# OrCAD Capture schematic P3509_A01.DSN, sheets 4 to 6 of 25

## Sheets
4 0021_M.2 KEY-M (NVME): size Custom
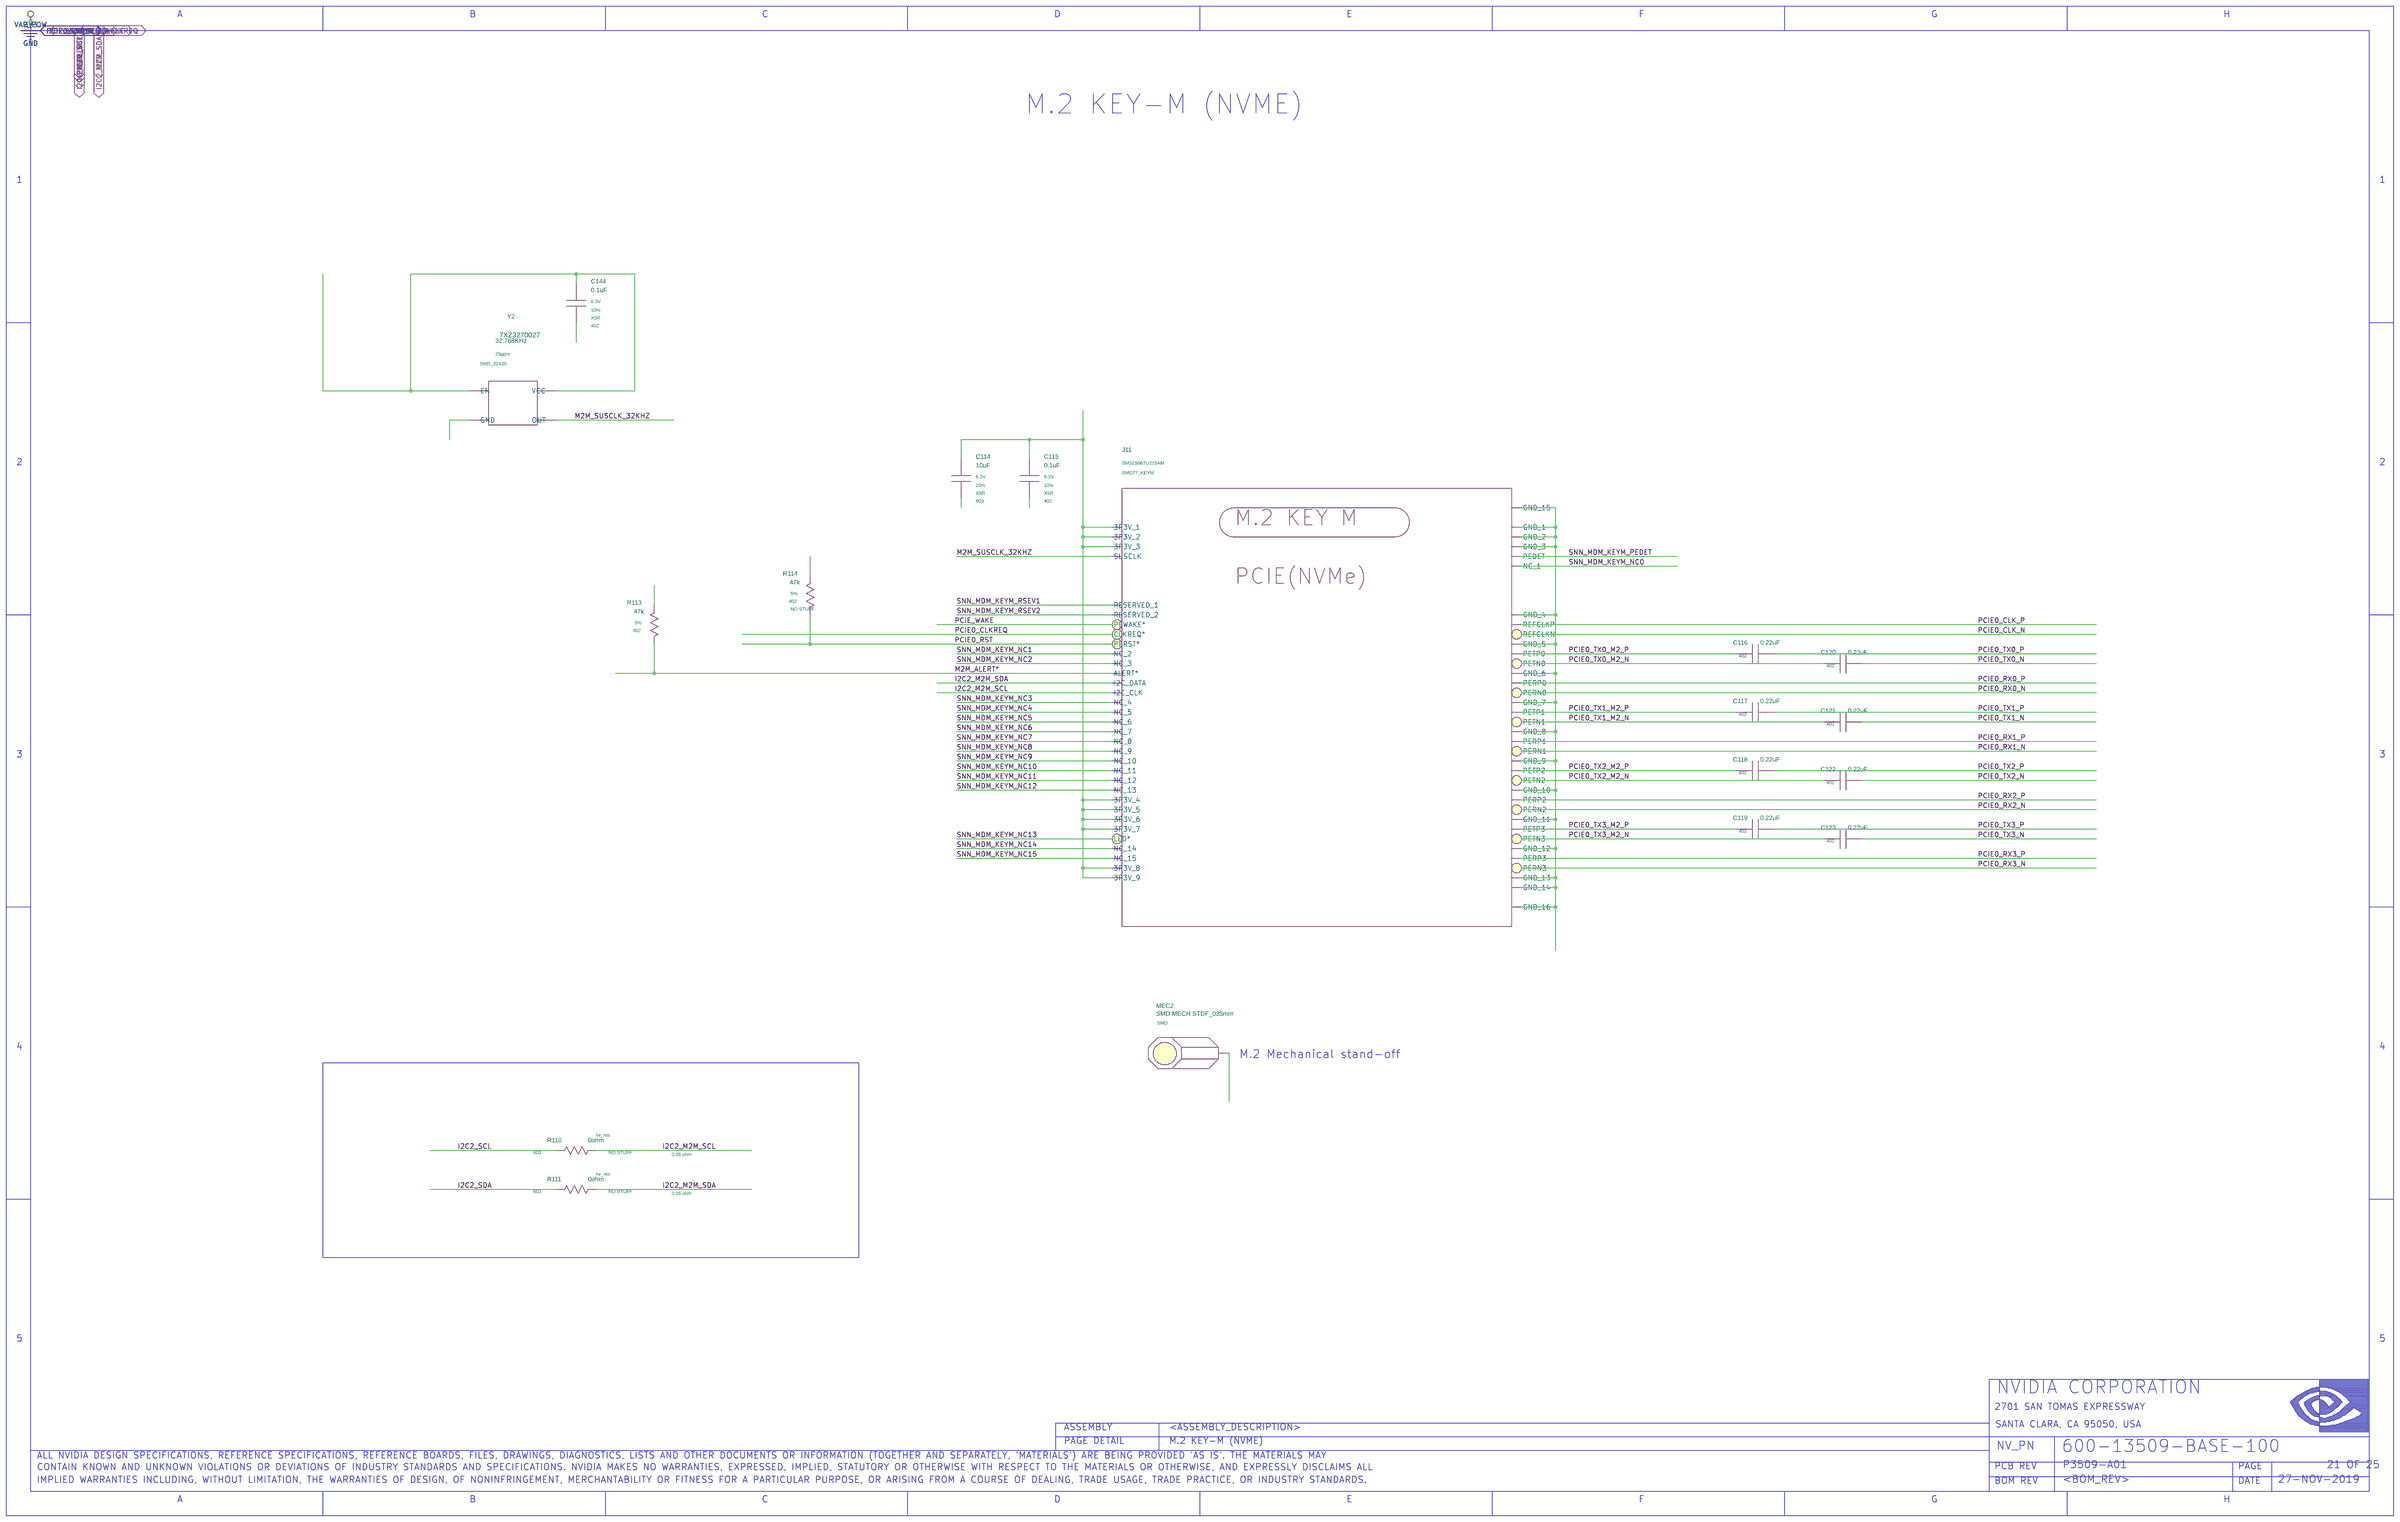
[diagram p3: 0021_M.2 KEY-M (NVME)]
5 0020_M.2 KEY-E (WIFI_BT): size Custom
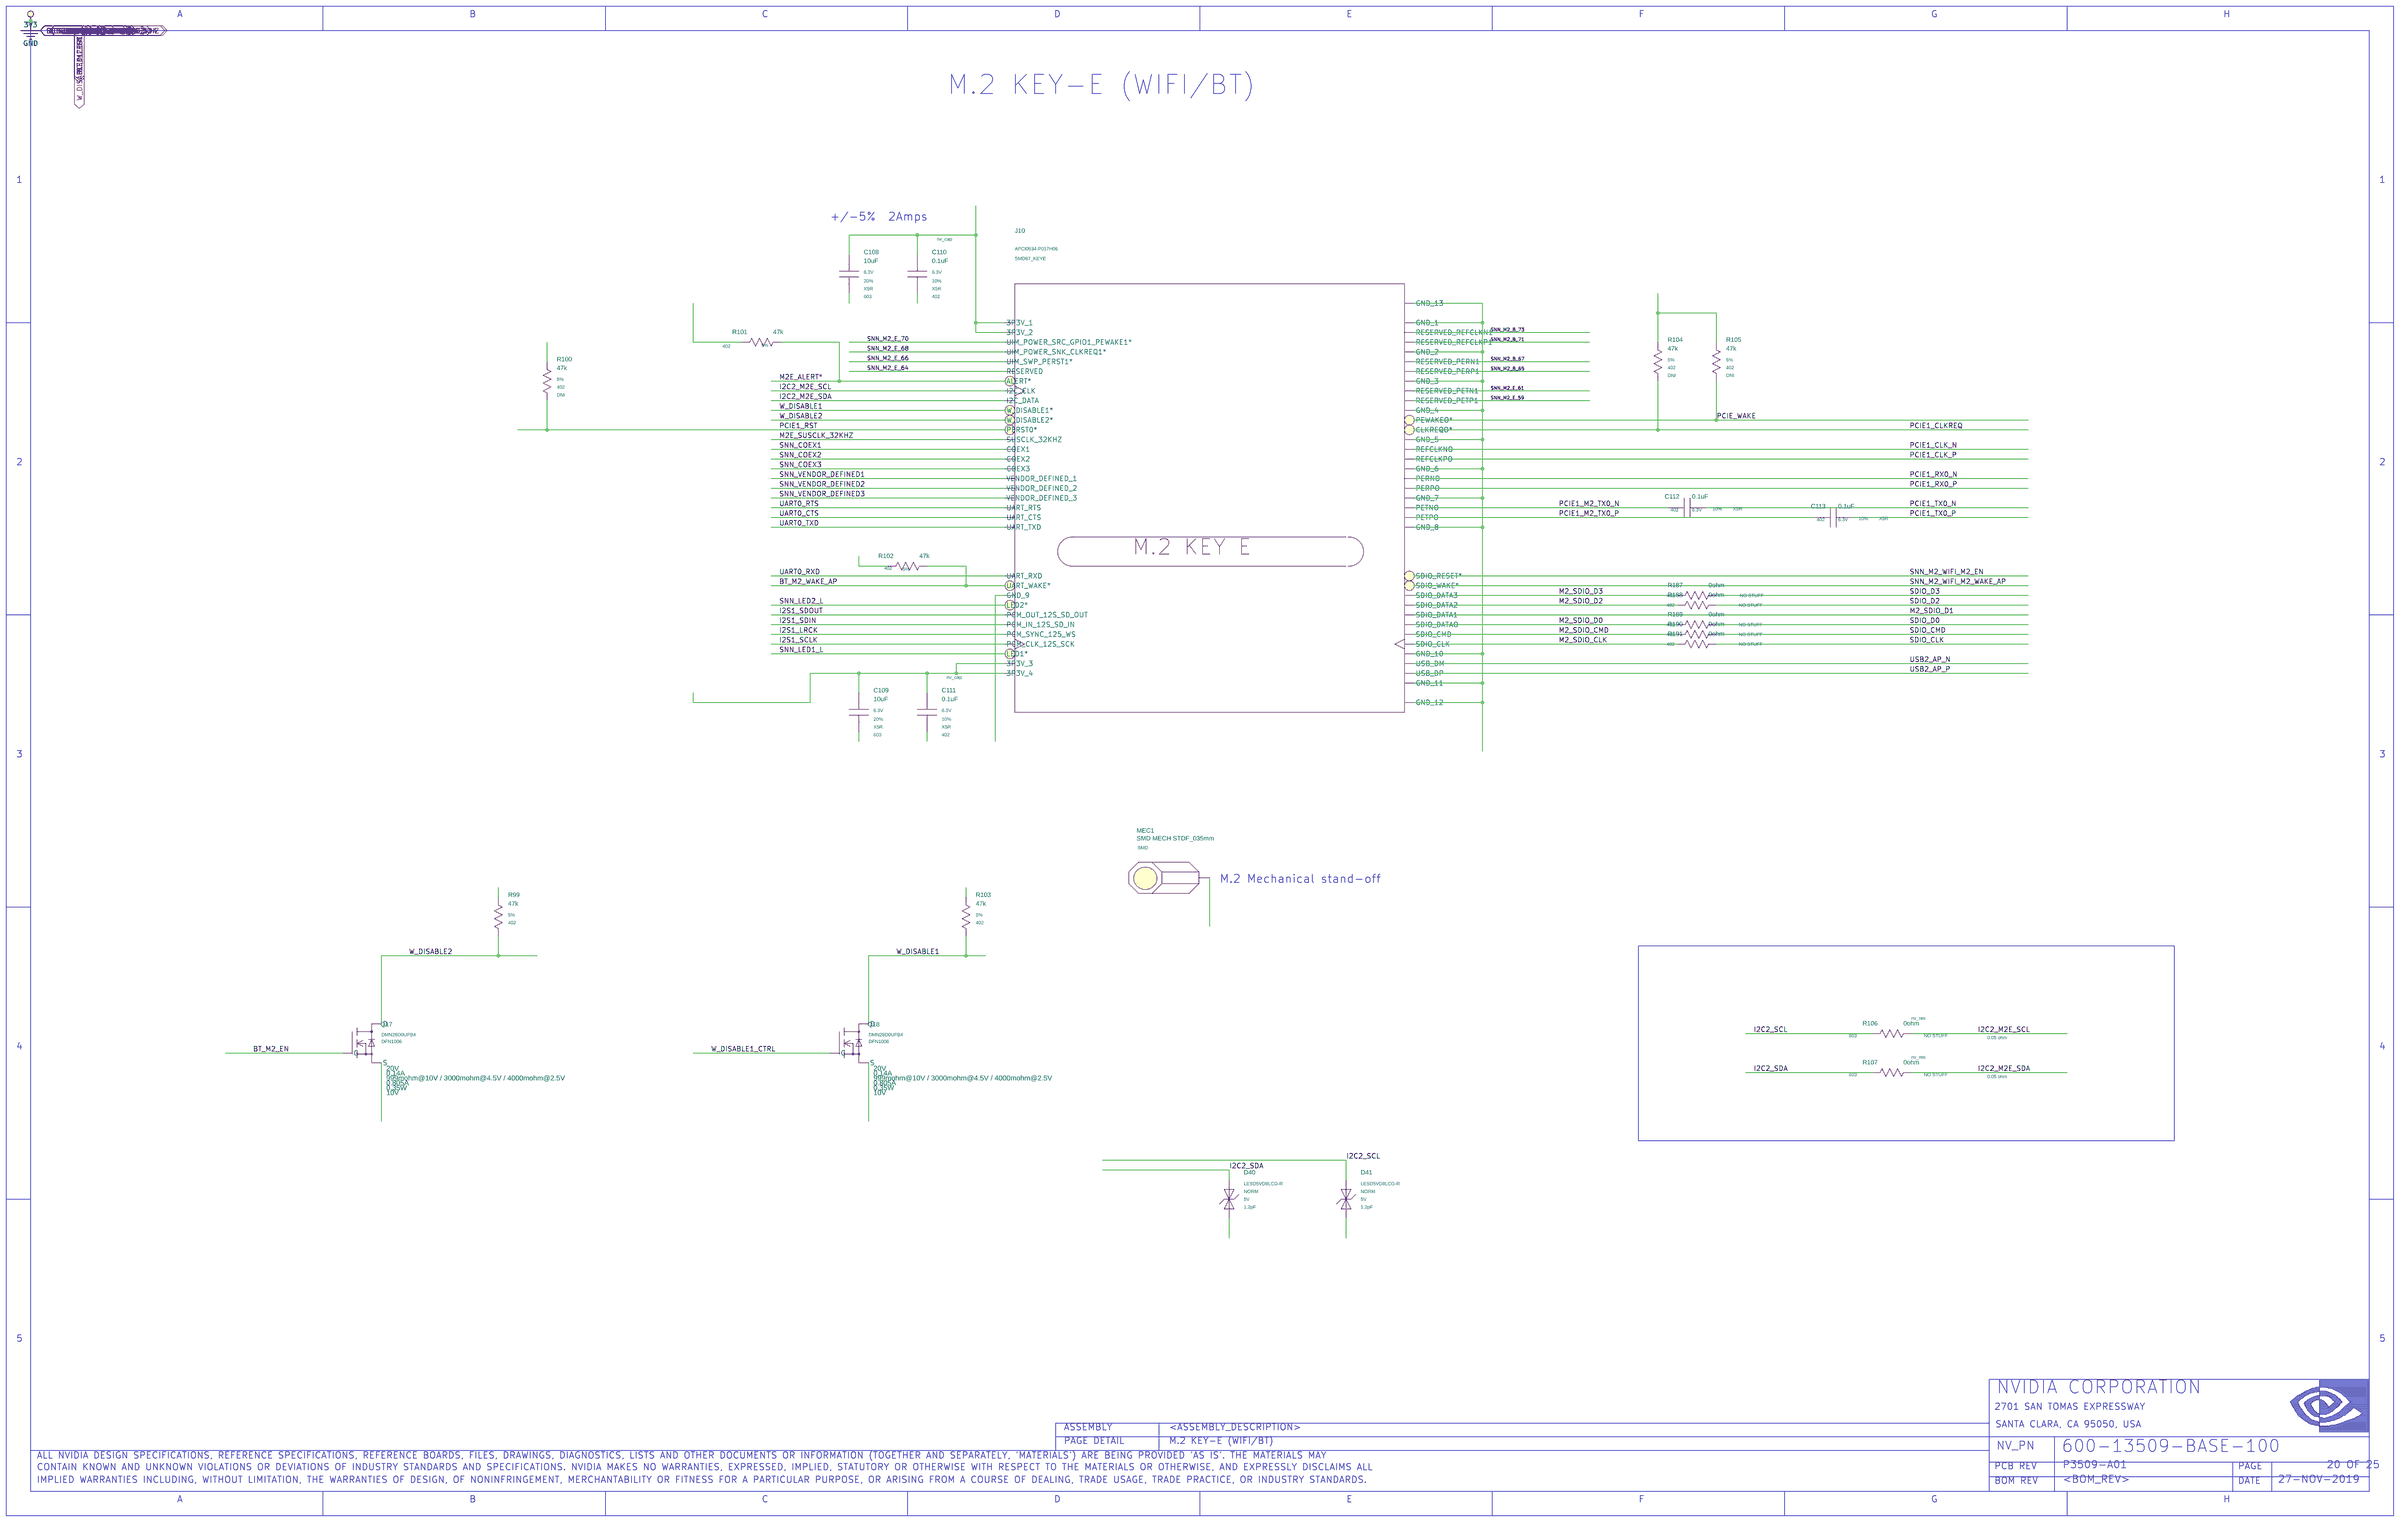
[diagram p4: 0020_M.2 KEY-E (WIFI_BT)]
6 0019_ETHERNET: size Custom
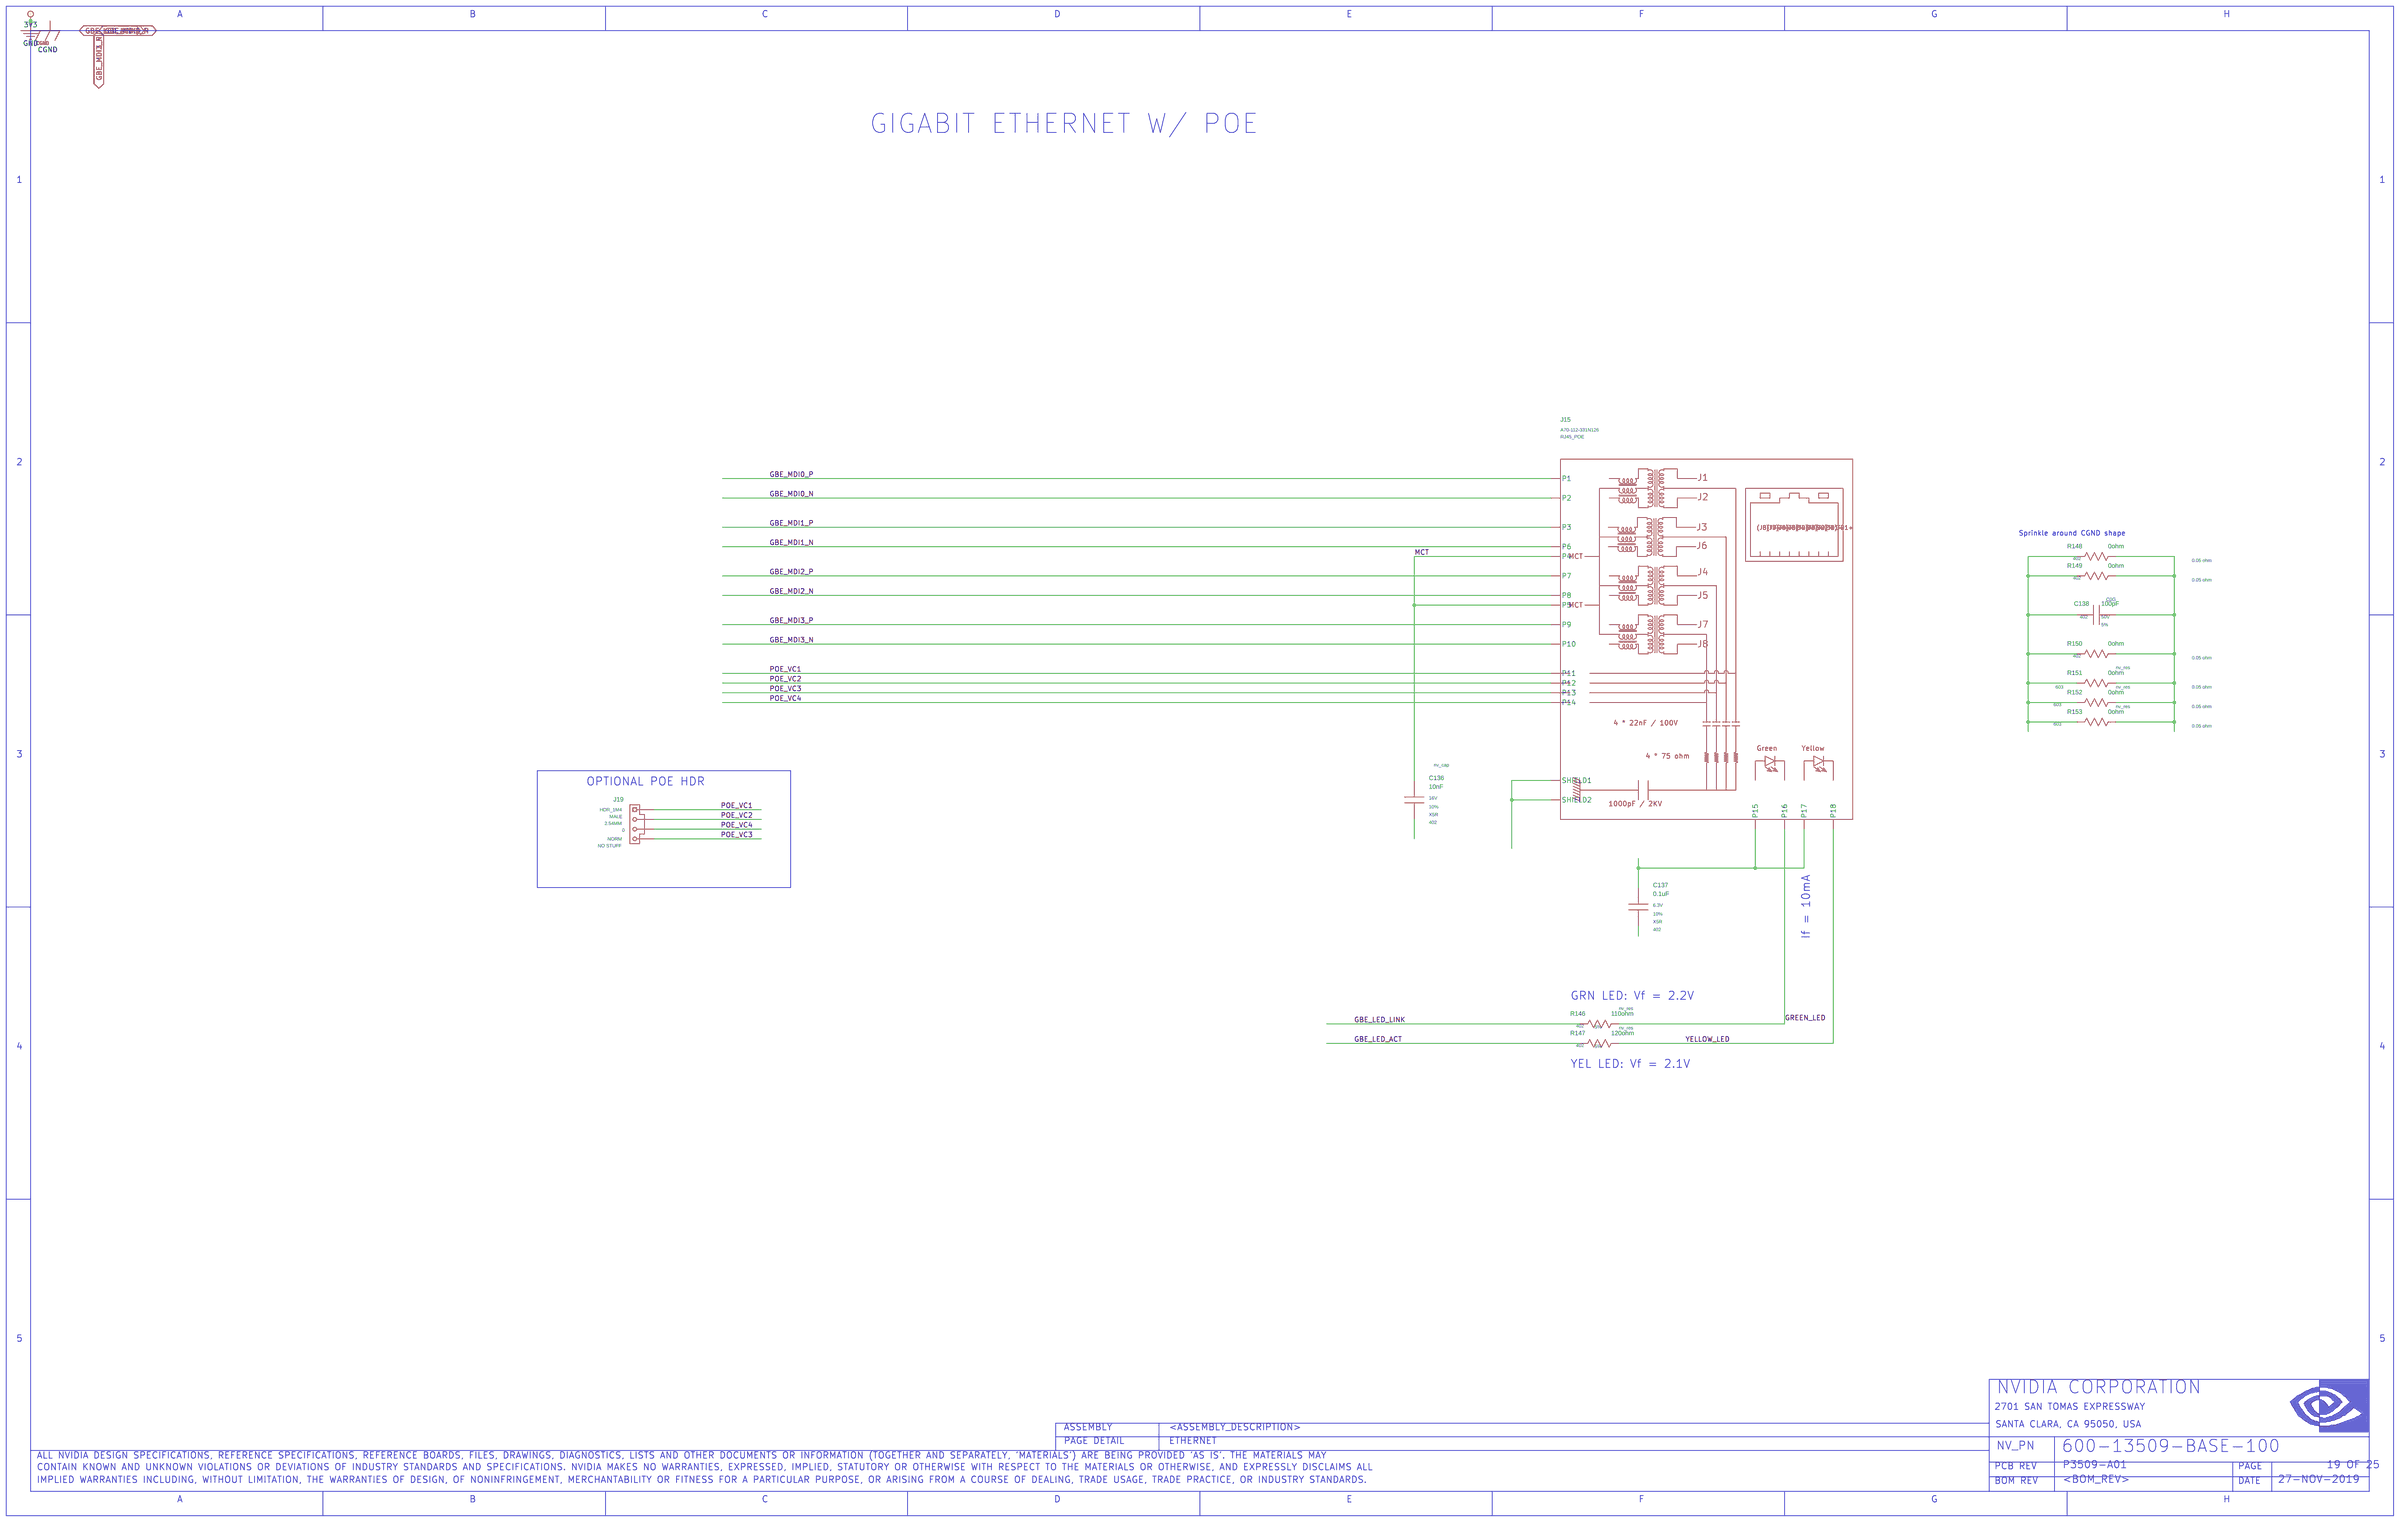
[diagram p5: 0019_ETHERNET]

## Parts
sheet 0019_ETHERNET
C136  10nF  [402]
C137  0.1uF  [402]
C138  100pF  [402]
J15  CON_RJ45  [CON_RJ45_018_TH_RA_F_2LED]
J19  HDR_1X4  [CON_HDR_001X004_TH_ST_M_P025]
R146  110ohm  [402]
R147  120ohm  [402]
R148  0ohm  [402]
R149  0ohm  [402]
R150  0ohm  [402]
R151  0ohm  [603]
R152  0ohm  [603]
R153  0ohm  [603]
sheet 0020_M.2 KEY-E (WIFI_BT)
C108  10uF  [603]
C109  10uF  [603]
C110  0.1uF  [402]
C111  0.1uF  [402]
C112  0.1uF  [402]
C113  0.1uF  [402]
D40  D_ESD  [DIODE_SMD_010X060]
D41  D_ESD  [DIODE_SMD_010X060]
J10  CON_M2_PCI_EXP  [CON_MINIPEX_067_SMT_RA_M2_KEYE_C]
MEC1  MEC_STANDOFF  [MEC_STANDOFF_PTH_620C380P]
Q17  Q_FET_N_ENH  [DFET_003_SMD_010X006_B]
Q18  Q_FET_N_ENH  [DFET_003_SMD_010X006_B]
R99  47k  [402]
R100  47k  [402]
R101  47k  [402]
R102  47k  [402]
R103  47k  [402]
R104  47k  [402]
R105  47k  [402]
R106  0ohm  [603]
R107  0ohm  [603]
R187  0ohm  [402]
R188  0ohm  [402]
R189  0ohm  [402]
R190  0ohm  [402]
R191  0ohm  [402]
sheet 0021_M.2 KEY-M (NVME)
C114  10uF  [603]
C115  0.1uF  [402]
C116  0.22uF  [402]
C117  0.22uF  [402]
C118  0.22uF  [402]
C119  0.22uF  [402]
C120  0.22uF  [402]
C121  0.22uF  [402]
C122  0.22uF  [402]
C123  0.22uF  [402]
C144  0.1uF  [402]
J11  CON_M2_PCI_EXP  [CON_MINIPEX_075_SMT_RA_M2_KEYM]
MEC2  MEC_STANDOFF  [MEC_STANDOFF_PTH_620C380P]
R110  0ohm  [603]
R111  0ohm  [603]
R113  47k  [402]
R114  47k  [402]
Y2  32.768KHz  [XTAL_SMD_4_032X025_D]

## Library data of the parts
C136 = C#1_v2: ASSEMBLY: ETHERNET; CDS_LIB: discrete; CDS_PART_NAME: C_0402-10NF,X5R,10%,16V,039-0024-000; CDS_PHYS_PART_NAME: C_0402-10NF,X5R,10%,16V,039-0024-000-039-0024-000,10NF; CDS_SEC: 1; CHIPS_PART_NAME: C; DEVICE_TYPENAME: C_0402-10NFX5R1016V039-0024-000-039-0024-00010NF; DRAWING: #NAME?; MAT: X5R; MAX_VOLTAGE: 16V; NV_PN: 039-0024-000; PATH: I15; PHYS_PAGE: 19; ROT: 0; SEC: 1; SIGNAL_MODEL: nv_cap; TOL: 10%; VER: 1; XY: (-4900,3550)
C137 = C#1_v2: ASSEMBLY: ETHERNET; CDS_LIB: discrete; CDS_PART_NAME: C_0402-0.1UF,X5R,10%,6.3V,039-0007-000; CDS_PHYS_PART_NAME: C_0402-0.1UF,X5R,10%,6.3V,039-0007-000-0.1UF,039-0007-000; CDS_SEC: 1; CHIPS_PART_NAME: C; DEVICE_TYPENAME: C_0402-01UFX5R1063V039-0007-000-01UF039-0007-000; DRAWING: #NAME?; ESL: N/A; ESR: N/A; MAT: X5R; MAX_VOLTAGE: 6.3V; NV_PN: 039-0007-000; PATH: I13; PHYS_PAGE: 19; ROT: 0; SEC: 1; SIGNAL_MODEL: nv_cap; TOL: 10%; VER: 1; XY: (-3750,3000)
C138 = C: ASSEMBLY: ETHERNET; CDS_LIB: discrete; CDS_PART_NAME: C_0402-100PF,C0G,5%,50V,035-0012-000; CDS_PHYS_PART_NAME: C_0402-100PF,C0G,5%,50V,035-0012-000-035-0012-000,100PF; CDS_SEC: 1; DEVICE_TYPENAME: C_0402-100PFC0G550V035-0012-000-035-0012-000100PF; DRAWING: #NAME?; ESL: N/A; ESR: N/A; MAT: C0G; MAX_VOLTAGE: 50V; NV_PN: 035-0012-000; PATH: I5; PHYS_PAGE: 19; ROT: 0; SEC: 1; SIGNAL_MODEL: nv_cap; TOL: 5%; VER: 2; XY: (-1400,4500)
J15 = CON_RJ45: ANGLE: 90; ASSEMBLY: ETHERNET; CDS_LIB: electro_mechanic; CDS_PART_NAME: CON_RJ45_RJ45_POE-A70-112-331N126,FEMALE,1.27MM,90,NO,YES,YES,YES,YES,54 V,600 MA,064-0373-000; CDS_PHYS_PART_NAME: CON_RJ45_RJ45_POE-A70-112-331N126,FEMALE,1.27MM,90,NO,YES,YES,YES,YES,54 V,600 MA,064-0373-000-064-0373-000; CDS_SEC: 1; DEVICE_TYPENAME: CON_RJ45_RJ45_POE-A70-112-331N126FEMALE127MM90NOYESYESYESYES54V600MA064-0373-000-064-0373-000; DRAWING: #NAME?; EMI_GROUND_TAB: YES; GENDER: FEMALE; LATCHING: YES; MAX_CURRENT: 600 mA; MAX_VOLTAGE: 54 V; NV_NAME: A70-112-331N126; NV_PN: 064-0373-000; PACK_TYPE: RJ45_POE; PATH: I1; PHYS_PAGE: 19; PITCH: 1.27mm; REFLOW: NO; ROT: 0; SEC: 1; SHIELDED: YES; SHROUDED: YES; VER: 15; XY: (-3400,4450)
J19 = HDR_1X4: ANGLE: 0; ASSEMBLY: ETHERNET; CDS_LIB: electro_mechanic; CDS_PART_NAME: HDR_1X4_NORM-HDR_1M4,MALE,2.54MM,0,NO,N/A,NO,500VAC,3A,074-0062-000; CDS_PHYS_PART_NAME: HDR_1X4_NORM-HDR_1M4,MALE,2.54MM,0,NO,N/A,NO,500VAC,3A,074-0062-000-074-0062-000; CDS_SEC: 1; DEVICE_TYPENAME: HDR_1X4_NORM-HDR_1M4MALE254MM0NONANO500VAC3A074-0062-000-074-0062-000; DRAWING: #NAME?; GENDER: MALE; LATCHING: NO; MAX_CURRENT: 3A; MAX_VOLTAGE: 500VAC; NV_NAME: HDR_1M4; NV_PN: 074-0062-000; PACK_TYPE: NORM; PATH: I29; PHYS_PAGE: 19; PITCH: 2.54MM; REFLOW: NO; ROT: 2; SEC: 1; SHROUDED: N/A; SKU: NO STUFF; VER: 1; XY: (-8900,3500)
R146 = R#1: ASSEMBLY: ETHERNET; CDS_LIB: discrete; CDS_PART_NAME: R_0402-110OHM,5 %,62.5MW,195-0492-000; CDS_PHYS_PART_NAME: R_0402-110OHM,5 %,62.5MW,195-0492-000-110OHM,195-0492-000; CDS_SEC: 1; CHIPS_PART_NAME: R; DEVICE_TYPENAME: R_0402-110OHM5625MW195-0492-000-110OHM195-0492-000; DRAWING: #NAME?; MAX_WATTAGE: 62.5mW; NV_PN: 195-0492-000; PATH: I17; PHYS_PAGE: 19; ROT: 0; SEC: 1; SIGNAL_MODEL: nv_res; TOL: 5%; VER: 1; XY: (-3950,2400)
R147 = R#1: ASSEMBLY: ETHERNET; CDS_LIB: discrete; CDS_PART_NAME: R_0402-120OHM,5 %,62.5MW,195-0499-000; CDS_PHYS_PART_NAME: R_0402-120OHM,5 %,62.5MW,195-0499-000-120OHM,195-0499-000; CDS_SEC: 1; CHIPS_PART_NAME: R; DEVICE_TYPENAME: R_0402-120OHM5625MW195-0499-000-120OHM195-0499-000; DRAWING: #NAME?; MAX_WATTAGE: 62.5mW; NV_PN: 195-0499-000; PATH: I18; PHYS_PAGE: 19; ROT: 0; SEC: 1; SIGNAL_MODEL: nv_res; TOL: 5%; VER: 1; XY: (-3950,2300)
R148 = R#1: ASSEMBLY: ETHERNET; CDS_LIB: discrete; CDS_PART_NAME: R_0402-0OHM,0.05 OHM,62.5MW,195-2655-000; CDS_PHYS_PART_NAME: R_0402-0OHM,0.05 OHM,62.5MW,195-2655-000-0OHM,195-2655-000; CDS_SEC: 1; CHIPS_PART_NAME: R; DEVICE_TYPENAME: R_0402-0OHM005OHM625MW195-2655-000-0OHM195-2655-000; DRAWING: #NAME?; MAX_WATTAGE: 62.5mW; NV_PN: 195-2655-000; PATH: I2; PHYS_PAGE: 19; ROT: 0; SEC: 1; SIGNAL_MODEL: nv_res; TOL: 0.05 ohm; VER: 1; XY: (-1400,4800)
R149 = R#1: ASSEMBLY: ETHERNET; CDS_LIB: discrete; CDS_PART_NAME: R_0402-0OHM,0.05 OHM,62.5MW,195-2655-000; CDS_PHYS_PART_NAME: R_0402-0OHM,0.05 OHM,62.5MW,195-2655-000-0OHM,195-2655-000; CDS_SEC: 1; CHIPS_PART_NAME: R; DEVICE_TYPENAME: R_0402-0OHM005OHM625MW195-2655-000-0OHM195-2655-000; DRAWING: #NAME?; MAX_WATTAGE: 62.5mW; NV_PN: 195-2655-000; PATH: I4; PHYS_PAGE: 19; ROT: 0; SEC: 1; SIGNAL_MODEL: nv_res; TOL: 0.05 ohm; VER: 1; XY: (-1400,4700)
R150 = R#1: ASSEMBLY: ETHERNET; CDS_LIB: discrete; CDS_PART_NAME: R_0402-0OHM,0.05 OHM,62.5MW,195-2655-000; CDS_PHYS_PART_NAME: R_0402-0OHM,0.05 OHM,62.5MW,195-2655-000-0OHM,195-2655-000; CDS_SEC: 1; CHIPS_PART_NAME: R; DEVICE_TYPENAME: R_0402-0OHM005OHM625MW195-2655-000-0OHM195-2655-000; DRAWING: #NAME?; MAX_WATTAGE: 62.5mW; NV_PN: 195-2655-000; PATH: I6; PHYS_PAGE: 19; ROT: 0; SEC: 1; SIGNAL_MODEL: nv_res; TOL: 0.05 ohm; VER: 1; XY: (-1400,4300)
R151 = R#1: ASSEMBLY: ETHERNET; CDS_LIB: discrete; CDS_PART_NAME: R_0603-0OHM,0.05 OHM,0MW,195-1765-000; CDS_PHYS_PART_NAME: R_0603-0OHM,0.05 OHM,0MW,195-1765-000-0OHM,195-1765-000; CDS_SEC: 1; CHIPS_PART_NAME: R; DEVICE_TYPENAME: R_0603-0OHM005OHM0MW195-1765-000-0OHM195-1765-000; DRAWING: #NAME?; MAX_WATTAGE: 0mW; NV_PN: 195-1765-000; PATH: I7; PHYS_PAGE: 19; ROT: 0; SEC: 1; SIGNAL_MODEL: nv_res; TOL: 0.05 ohm; VER: 1; XY: (-1400,4150)
R152 = R#1: ASSEMBLY: ETHERNET; CDS_LIB: discrete; CDS_PART_NAME: R_0603-0OHM,0.05 OHM,0MW,195-1765-000; CDS_PHYS_PART_NAME: R_0603-0OHM,0.05 OHM,0MW,195-1765-000-0OHM,195-1765-000; CDS_SEC: 1; CHIPS_PART_NAME: R; DEVICE_TYPENAME: R_0603-0OHM005OHM0MW195-1765-000-0OHM195-1765-000; DRAWING: #NAME?; MAX_WATTAGE: 0mW; NV_PN: 195-1765-000; PATH: I8; PHYS_PAGE: 19; ROT: 0; SEC: 1; SIGNAL_MODEL: nv_res; TOL: 0.05 ohm; VER: 1; XY: (-1400,4050)
R153 = R#1: ASSEMBLY: ETHERNET; CDS_LIB: discrete; CDS_PART_NAME: R_0603-0OHM,0.05 OHM,0MW,195-1765-000; CDS_PHYS_PART_NAME: R_0603-0OHM,0.05 OHM,0MW,195-1765-000-0OHM,195-1765-000; CDS_SEC: 1; CHIPS_PART_NAME: R; DEVICE_TYPENAME: R_0603-0OHM005OHM0MW195-1765-000-0OHM195-1765-000; DRAWING: #NAME?; MAX_WATTAGE: 0mW; NV_PN: 195-1765-000; PATH: I9; PHYS_PAGE: 19; ROT: 0; SEC: 1; SIGNAL_MODEL: nv_res; TOL: 0.05 ohm; VER: 1; XY: (-1400,3950)
C108 = C#1_v2: ASSEMBLY: M2_WIFIBT; CDS_LIB: discrete; CDS_PART_NAME: C_0603-10UF,X5R,20%,6.3V,039-0135-000; CDS_PHYS_PART_NAME: C_0603-10UF,X5R,20%,6.3V,039-0135-000-039-0135-000,10UF; CDS_SEC: 1; CHIPS_PART_NAME: C; DEVICE_TYPENAME: C_0603-10UFX5R2063V039-0135-000-039-0135-00010UF; DRAWING: #NAME?; MAT: X5R; MAX_VOLTAGE: 6.3V; NV_PN: 039-0135-000; PATH: I26; PHYS_PAGE: 20; ROT: 0; SEC: 1; SIGNAL_MODEL: DEFAULT_CAPACITOR_1e+07pF_2_1; TOL: 20%; VER: 1; XY: (-7800,6250)
C109 = C#1_v2: ASSEMBLY: M2_WIFIBT; CDS_LIB: discrete; CDS_PART_NAME: C_0603-10UF,X5R,20%,6.3V,039-0135-000; CDS_PHYS_PART_NAME: C_0603-10UF,X5R,20%,6.3V,039-0135-000-039-0135-000,10UF; CDS_SEC: 1; CHIPS_PART_NAME: C; DEVICE_TYPENAME: C_0603-10UFX5R2063V039-0135-000-039-0135-00010UF; DRAWING: #NAME?; MAT: X5R; MAX_VOLTAGE: 6.3V; NV_PN: 039-0135-000; PATH: I36; PHYS_PAGE: 20; ROT: 0; SEC: 1; SIGNAL_MODEL: DEFAULT_CAPACITOR_1e+07pF_2_1; TOL: 20%; VER: 1; XY: (-7750,4000)
C110 = C#1_v2: ASSEMBLY: M2_WIFIBT; CDS_LIB: discrete; CDS_PART_NAME: C_0402-0.1UF,X5R,10%,6.3V,039-0007-000; CDS_PHYS_PART_NAME: C_0402-0.1UF,X5R,10%,6.3V,039-0007-000-0.1UF,039-0007-000; CDS_SEC: 1; CHIPS_PART_NAME: C; DEVICE_TYPENAME: C_0402-01UFX5R1063V039-0007-000-01UF039-0007-000; DRAWING: #NAME?; MAT: X5R; MAX_VOLTAGE: 6.3V; NV_PN: 039-0007-000; PATH: I25; PHYS_PAGE: 20; ROT: 0; SEC: 1; SIGNAL_MODEL: nv_cap; TOL: 10%; VER: 1; XY: (-7450,6250)
C111 = C#1_v2: ASSEMBLY: M2_WIFIBT; CDS_LIB: discrete; CDS_PART_NAME: C_0402-0.1UF,X5R,10%,6.3V,039-0007-000; CDS_PHYS_PART_NAME: C_0402-0.1UF,X5R,10%,6.3V,039-0007-000-0.1UF,039-0007-000; CDS_SEC: 1; CHIPS_PART_NAME: C; DEVICE_TYPENAME: C_0402-01UFX5R1063V039-0007-000-01UF039-0007-000; DRAWING: #NAME?; MAT: X5R; MAX_VOLTAGE: 6.3V; NV_PN: 039-0007-000; PATH: I34; PHYS_PAGE: 20; ROT: 0; SEC: 1; SIGNAL_MODEL: nv_cap; TOL: 10%; VER: 1; XY: (-7400,4000)
C112 = C: ASSEMBLY: M2_WIFIBT; CDS_LIB: discrete; CDS_PART_NAME: C_0402-0.1UF,X5R,10%,6.3V,039-0007-000; CDS_PHYS_PART_NAME: C_0402-0.1UF,X5R,10%,6.3V,039-0007-000-0.1UF,039-0007-000; CDS_SEC: 1; DEVICE_TYPENAME: C_0402-01UFX5R1063V039-0007-000-01UF039-0007-000; DRAWING: #NAME?; MAT: X5R; MAX_VOLTAGE: 6.3V; NV_PN: 039-0007-000; PATH: I16; PHYS_PAGE: 20; ROT: 0; SEC: 1; SIGNAL_MODEL: nv_cap; TOL: 10%; VER: 2; XY: (-3500,5050)
C113 = C: ASSEMBLY: M2_WIFIBT; CDS_LIB: discrete; CDS_PART_NAME: C_0402-0.1UF,X5R,10%,6.3V,039-0007-000; CDS_PHYS_PART_NAME: C_0402-0.1UF,X5R,10%,6.3V,039-0007-000-0.1UF,039-0007-000; CDS_SEC: 1; DEVICE_TYPENAME: C_0402-01UFX5R1063V039-0007-000-01UF039-0007-000; DRAWING: #NAME?; MAT: X5R; MAX_VOLTAGE: 6.3V; NV_PN: 039-0007-000; PATH: I17; PHYS_PAGE: 20; ROT: 0; SEC: 1; SIGNAL_MODEL: nv_cap; TOL: 10%; VER: 2; XY: (-2750,5000)
D40 = D_ESD: ASSEMBLY: M2_WIFIBT; BREAKDOWN_VOLTAGE_MIN_TYP: 5.5V; CAPACITANCE_MAX_TYP: 1.2pF; CDS_LIB: discrete; CDS_PART_NAME: D_ESD_NORM-LESD5VD8LCG-R,1 LINE,BI-DIRECTIONAL,5V,0.05UA,5.5V,10V@2A,1.2PF,090-0172-000; CDS_PHYS_PART_NAME: D_ESD_NORM-LESD5VD8LCG-R,1 LINE,BI-DIRECTIONAL,5V,0.05UA,5.5V,10V@2A,1.2PF,090-0172-000-090-0172-000; CDS_SEC: 1; CLAMPING_VOLTAGE: 10V@2A; CONFIGURATION: 1 Line; DEVICE_TYPENAME: D_ESD_NORM-LESD5VD8LCG-R1LINEBI-DIRECTIONAL5V005UA55V10V2A12PF090-0172-000-090-0172-000; DRAWING: #NAME?; MAX_REVERSE_LEAKAGE_CURRENT: 0.05uA; MAX_REVERSE_VOLTAGE: 5V; NV_NAME: LESD5VD8LCG-R; NV_PN: 090-0172-000; PACK_TYPE: NORM; PATH: I40; PHYS_PAGE: 20; POLARITY: Bi-Directional; ROT: 0; SEC: 1; VER: 2; XY: (-5850,1500)
D41 = D_ESD: ASSEMBLY: M2_WIFIBT; BREAKDOWN_VOLTAGE_MIN_TYP: 5.5V; CAPACITANCE_MAX_TYP: 1.2pF; CDS_LIB: discrete; CDS_PART_NAME: D_ESD_NORM-LESD5VD8LCG-R,1 LINE,BI-DIRECTIONAL,5V,0.05UA,5.5V,10V@2A,1.2PF,090-0172-000; CDS_PHYS_PART_NAME: D_ESD_NORM-LESD5VD8LCG-R,1 LINE,BI-DIRECTIONAL,5V,0.05UA,5.5V,10V@2A,1.2PF,090-0172-000-090-0172-000; CDS_SEC: 1; CLAMPING_VOLTAGE: 10V@2A; CONFIGURATION: 1 Line; DEVICE_TYPENAME: D_ESD_NORM-LESD5VD8LCG-R1LINEBI-DIRECTIONAL5V005UA55V10V2A12PF090-0172-000-090-0172-000; DRAWING: #NAME?; MAX_REVERSE_LEAKAGE_CURRENT: 0.05uA; MAX_REVERSE_VOLTAGE: 5V; NV_NAME: LESD5VD8LCG-R; NV_PN: 090-0172-000; PACK_TYPE: NORM; PATH: I38; PHYS_PAGE: 20; POLARITY: Bi-Directional; ROT: 0; SEC: 1; VER: 2; XY: (-5250,1500)
J10 = CON_M2_PCI_EXP: ANGLE: 90; ASSEMBLY: M2_WIFIBT; CDS_LIB: electro_mechanic; CDS_PART_NAME: CON_M2_PCI_EXP_SMD67_KEYE-APCI0534-P017H06,FEMALE,0.5MM,90,YES,NO,NO,NO,NO,50 V,0.5 A,080-1761-000; CDS_PHYS_PART_NAME: CON_M2_PCI_EXP_SMD67_KEYE-APCI0534-P017H06,FEMALE,0.5MM,90,YES,NO,NO,NO,NO,50 V,0.5 A,080-1761-000-080-1761-000; CDS_SEC: 1; DEVICE_TYPENAME: CON_M2_PCI_EXP_SMD67_KEYE-APCI0534-P017H06FEMALE05MM90YESNONONONO50V05A080-1761-000-080-1761-000; DRAWING: #NAME?; EMI_GROUND_TAB: NO; GENDER: FEMALE; LATCHING: NO; MAX_CURRENT: 0.5 A; MAX_VOLTAGE: 50 V; NV_NAME: APCI0534-P017H06; NV_PN: 080-1761-000; PACK_TYPE: SMD67_KEYE; PATH: I1; PHYS_PAGE: 20; PITCH: 0.5mm; REFLOW: YES; ROT: 0; SEC: 1; SHIELDED: NO; SHROUDED: NO; VER: 2; XY: (-5950,5100)
MEC1 = MEC_STANDOFF: ASSEMBLY: M2_WIFIBT; CDS_LIB: mechanic; CDS_PART_NAME: MEC_STANDOFF_SMD-SMD MECH STDF_035MM,155-0879-000; CDS_PHYS_PART_NAME: MEC_STANDOFF_SMD-SMD MECH STDF_035MM,155-0879-000-155-0879-000; CDS_SEC: 1; DEVICE_TYPENAME: MEC_STANDOFF_SMD-SMDMECHSTDF_035MM155-0879-000-155-0879-000; DRAWING: #NAME?; NV_NAME: SMD MECH STDF_035mm; NV_PN: 155-0879-000; PACK_TYPE: SMD; PATH: I89; PHYS_PAGE: 20; ROT: 0; SEC: 1; SEC_TYPE: SMD; VER: 2; XY: (-6150,3150)
Q17 = Q_FET_N_ENH#1: ASSEMBLY: M2_WIFIBT; CDS_LIB: discrete; CDS_PART_NAME: Q_FET_N_ENH_DFN1006-DMN26D0UFB4,20V,999MOHM@10V / 3000MOHM@4.5V / 4000MOHM@2.5V,0.14A,0.805A,10V,0.35W,999NC@10V / 0NC@4.5V / A; CDS_PHYS_PART_NAME: Q_FET_N_ENH_DFN1006-DMN26D0UFB4,20V,999MOHM@10V / 3000MOHM@4.5V / 4000MOHM@2.5V,0.14A,0.805A,10V,0.35W,999NC@10V / 0NC@4.5V / B; CDS_SEC: 1; CONTINUOUS_CURRENT: 0.14A; CaptureCellPackProp: Q_FET_N_ENH##1; DEVICE_TYPENAME: Q_FET_N_ENH_DFN1006-DMN26D0UFB420V999MOHM10V3000MOHM45V4000MOHM25V014A0805A10V035W999NC10V0NC45VB; DRAWING: #NAME?; MAX_CURRENT: 0.805A; MAX_VOLTAGE: 20V; MAX_WATTAGE: 0.35W; NV_NAME: DMN26D0UFB4; NV_PN: 300-0868-000; PACK_TYPE: DFN1006; PATH: I73; PHYS_PAGE: 20; Q_G: 999nC@10V / 0nC@4.5V / 999nC@2.5V; ROT: 0; R_DS_ON: 999mohm@10V / 3000mohm@4.5V / 4000mohm@2.5V; SEC: 1; VER: 2; V_BE_GS: 10V; XY: (-10300,2300)
Q18 = Q_FET_N_ENH#1: ASSEMBLY: M2_WIFIBT; CDS_LIB: discrete; CDS_PART_NAME: Q_FET_N_ENH_DFN1006-DMN26D0UFB4,20V,999MOHM@10V / 3000MOHM@4.5V / 4000MOHM@2.5V,0.14A,0.805A,10V,0.35W,999NC@10V / 0NC@4.5V / A; CDS_PHYS_PART_NAME: Q_FET_N_ENH_DFN1006-DMN26D0UFB4,20V,999MOHM@10V / 3000MOHM@4.5V / 4000MOHM@2.5V,0.14A,0.805A,10V,0.35W,999NC@10V / 0NC@4.5V / B; CDS_SEC: 1; CONTINUOUS_CURRENT: 0.14A; CaptureCellPackProp: Q_FET_N_ENH##1; DEVICE_TYPENAME: Q_FET_N_ENH_DFN1006-DMN26D0UFB420V999MOHM10V3000MOHM45V4000MOHM25V014A0805A10V035W999NC10V0NC45VB; DRAWING: #NAME?; MAX_CURRENT: 0.805A; MAX_VOLTAGE: 20V; MAX_WATTAGE: 0.35W; NV_NAME: DMN26D0UFB4; NV_PN: 300-0868-000; PACK_TYPE: DFN1006; PATH: I44; PHYS_PAGE: 20; Q_G: 999nC@10V / 0nC@4.5V / 999nC@2.5V; ROT: 0; R_DS_ON: 999mohm@10V / 3000mohm@4.5V / 4000mohm@2.5V; SEC: 1; VER: 2; V_BE_GS: 10V; XY: (-7800,2300)
R99 = R: ASSEMBLY: M2_WIFIBT; CDS_LIB: discrete; CDS_PART_NAME: R_0402-47K,5 %,62.5MW,195-0599-000; CDS_PHYS_PART_NAME: R_0402-47K,5 %,62.5MW,195-0599-000-195-0599-000,47K; CDS_SEC: 1; DEVICE_TYPENAME: R_0402-47K5625MW195-0599-000-195-0599-00047K; DRAWING: #NAME?; MAX_WATTAGE: 62.5mW; NV_PN: 195-0599-000; PATH: I72; PHYS_PAGE: 20; ROT: 0; SEC: 1; SIGNAL_MODEL: nv_res; TOL: 5%; VER: 2; XY: (-9600,2950)
R100 = R: ASSEMBLY: M2_WIFIBT; CDS_LIB: discrete; CDS_PART_NAME: R_0402-47K,5 %,62.5MW,195-0599-000; CDS_PHYS_PART_NAME: R_0402-47K,5 %,62.5MW,195-0599-000-195-0599-000,47K; CDS_SEC: 1; DEVICE_TYPENAME: R_0402-47K5625MW195-0599-000-195-0599-00047K; DRAWING: #NAME?; MAX_WATTAGE: 62.5mW; NV_PN: 195-0599-000; PATH: I52; PHYS_PAGE: 20; ROT: 0; SEC: 1; SIGNAL_MODEL: nv_res; SKU: DNI; TOL: 5%; VER: 2; XY: (-9350,5700)
R101 = R#1: ASSEMBLY: M2_WIFIBT; CDS_LIB: discrete; CDS_PART_NAME: R_0402-47K,5 %,62.5MW,195-0599-000; CDS_PHYS_PART_NAME: R_0402-47K,5 %,62.5MW,195-0599-000-195-0599-000,47K; CDS_SEC: 1; CHIPS_PART_NAME: R; DEVICE_TYPENAME: R_0402-47K5625MW195-0599-000-195-0599-00047K; DRAWING: #NAME?; MAX_WATTAGE: 62.5mW; NV_PN: 195-0599-000; PATH: I47; PHYS_PAGE: 20; ROT: 0; SEC: 1; SIGNAL_MODEL: nv_res; TOL: 5%; VER: 1; XY: (-8250,5900)
R102 = R#1: ASSEMBLY: M2_WIFIBT; CDS_LIB: discrete; CDS_PART_NAME: R_0402-47K,5 %,62.5MW,195-0599-000; CDS_PHYS_PART_NAME: R_0402-47K,5 %,62.5MW,195-0599-000-195-0599-000,47K; CDS_SEC: 1; CHIPS_PART_NAME: R; DEVICE_TYPENAME: R_0402-47K5625MW195-0599-000-195-0599-00047K; DRAWING: #NAME?; MAX_WATTAGE: 62.5mW; NV_PN: 195-0599-000; PATH: I30; PHYS_PAGE: 20; ROT: 0; SEC: 1; SIGNAL_MODEL: nv_res; TOL: 5%; VER: 1; XY: (-7500,4750)
R103 = R: ASSEMBLY: M2_WIFIBT; CDS_LIB: discrete; CDS_PART_NAME: R_0402-47K,5 %,62.5MW,195-0599-000; CDS_PHYS_PART_NAME: R_0402-47K,5 %,62.5MW,195-0599-000-195-0599-000,47K; CDS_SEC: 1; DEVICE_TYPENAME: R_0402-47K5625MW195-0599-000-195-0599-00047K; DRAWING: #NAME?; MAX_WATTAGE: 62.5mW; NV_PN: 195-0599-000; PATH: I43; PHYS_PAGE: 20; ROT: 0; SEC: 1; SIGNAL_MODEL: nv_res; TOL: 5%; VER: 2; XY: (-7200,2950)
R104 = R: ASSEMBLY: M2_WIFIBT; CDS_LIB: discrete; CDS_PART_NAME: R_0402-47K,5 %,62.5MW,195-0599-000; CDS_PHYS_PART_NAME: R_0402-47K,5 %,62.5MW,195-0599-000-195-0599-000,47K; CDS_SEC: 1; DEVICE_TYPENAME: R_0402-47K5625MW195-0599-000-195-0599-00047K; DRAWING: #NAME?; MAX_WATTAGE: 62.5mW; NV_PN: 195-0599-000; PATH: I15; PHYS_PAGE: 20; ROT: 0; SEC: 1; SIGNAL_MODEL: nv_res; SKU: DNI; TOL: 5%; VER: 2; XY: (-3650,5800)
R105 = R: ASSEMBLY: M2_WIFIBT; CDS_LIB: discrete; CDS_PART_NAME: R_0402-47K,5 %,62.5MW,195-0599-000; CDS_PHYS_PART_NAME: R_0402-47K,5 %,62.5MW,195-0599-000-195-0599-000,47K; CDS_SEC: 1; DEVICE_TYPENAME: R_0402-47K5625MW195-0599-000-195-0599-00047K; DRAWING: #NAME?; MAX_WATTAGE: 62.5mW; NV_PN: 195-0599-000; PATH: I14; PHYS_PAGE: 20; ROT: 0; SEC: 1; SIGNAL_MODEL: nv_res; SKU: DNI; TOL: 5%; VER: 2; XY: (-3350,5800)
R106 = R#1: ASSEMBLY: M2_WIFIBT; CDS_LIB: discrete; CDS_PART_NAME: R_0603-0OHM,0.05 OHM,0MW,195-1765-000; CDS_PHYS_PART_NAME: R_0603-0OHM,0.05 OHM,0MW,195-1765-000-0OHM,195-1765-000; CDS_SEC: 1; CHIPS_PART_NAME: R; DEVICE_TYPENAME: R_0603-0OHM005OHM0MW195-1765-000-0OHM195-1765-000; DRAWING: #NAME?; MAX_WATTAGE: 0mW; NO_XNET_CONNECTION: 0; NV_PN: 195-1765-000; PATH: I20; PHYS_PAGE: 20; ROT: 0; SEC: 1; SIGNAL_MODEL: nv_res; SKU: NO STUFF; TOL: 0.05 ohm; VER: 1; XY: (-2450,2350)
R107 = R#1: ASSEMBLY: M2_WIFIBT; CDS_LIB: discrete; CDS_PART_NAME: R_0603-0OHM,0.05 OHM,0MW,195-1765-000; CDS_PHYS_PART_NAME: R_0603-0OHM,0.05 OHM,0MW,195-1765-000-0OHM,195-1765-000; CDS_SEC: 1; CHIPS_PART_NAME: R; DEVICE_TYPENAME: R_0603-0OHM005OHM0MW195-1765-000-0OHM195-1765-000; DRAWING: #NAME?; MAX_WATTAGE: 0mW; NO_XNET_CONNECTION: 0; NV_PN: 195-1765-000; PATH: I21; PHYS_PAGE: 20; ROT: 0; SEC: 1; SIGNAL_MODEL: nv_res; SKU: NO STUFF; TOL: 0.05 ohm; VER: 1; XY: (-2450,2150)
R187 = R#1: ASSEMBLY: M2_WIFIBT; CDS_LIB: discrete; CDS_PART_NAME: R_0402-0OHM,0.05 OHM,62.5MW,195-2655-000; CDS_PHYS_PART_NAME: R_0402-0OHM,0.05 OHM,62.5MW,195-2655-000-0OHM,195-2655-000; CDS_SEC: 1; CHIPS_PART_NAME: R; DEVICE_TYPENAME: R_0402-0OHM005OHM625MW195-2655-000-0OHM195-2655-000; DRAWING: #NAME?; MAX_WATTAGE: 62.5mW; NV_PN: 195-2655-000; PATH: I77; PHYS_PAGE: 20; ROT: 0; SEC: 1; SKU: NO STUFF; TOL: 0.05 ohm; VER: 1; XY: (-3450,4600)
R188 = R#1: ASSEMBLY: M2_WIFIBT; CDS_LIB: discrete; CDS_PART_NAME: R_0402-0OHM,0.05 OHM,62.5MW,195-2655-000; CDS_PHYS_PART_NAME: R_0402-0OHM,0.05 OHM,62.5MW,195-2655-000-0OHM,195-2655-000; CDS_SEC: 1; CHIPS_PART_NAME: R; DEVICE_TYPENAME: R_0402-0OHM005OHM625MW195-2655-000-0OHM195-2655-000; DRAWING: #NAME?; MAX_WATTAGE: 62.5mW; NV_PN: 195-2655-000; PATH: I78; PHYS_PAGE: 20; ROT: 0; SEC: 1; SKU: NO STUFF; TOL: 0.05 ohm; VER: 1; XY: (-3450,4550)
R189 = R#1: ASSEMBLY: M2_WIFIBT; CDS_LIB: discrete; CDS_PART_NAME: R_0402-0OHM,0.05 OHM,62.5MW,195-2655-000; CDS_PHYS_PART_NAME: R_0402-0OHM,0.05 OHM,62.5MW,195-2655-000-0OHM,195-2655-000; CDS_SEC: 1; CHIPS_PART_NAME: R; DEVICE_TYPENAME: R_0402-0OHM005OHM625MW195-2655-000-0OHM195-2655-000; DRAWING: #NAME?; MAX_WATTAGE: 62.5mW; NV_PN: 195-2655-000; PATH: I80; PHYS_PAGE: 20; ROT: 0; SEC: 1; SKU: NO STUFF; TOL: 0.05 ohm; VER: 1; XY: (-3450,4450)
R190 = R#1: ASSEMBLY: M2_WIFIBT; CDS_LIB: discrete; CDS_PART_NAME: R_0402-0OHM,0.05 OHM,62.5MW,195-2655-000; CDS_PHYS_PART_NAME: R_0402-0OHM,0.05 OHM,62.5MW,195-2655-000-0OHM,195-2655-000; CDS_SEC: 1; CHIPS_PART_NAME: R; DEVICE_TYPENAME: R_0402-0OHM005OHM625MW195-2655-000-0OHM195-2655-000; DRAWING: #NAME?; MAX_WATTAGE: 62.5mW; NV_PN: 195-2655-000; PATH: I81; PHYS_PAGE: 20; ROT: 0; SEC: 1; SKU: NO STUFF; TOL: 0.05 ohm; VER: 1; XY: (-3450,4400)
R191 = R#1: ASSEMBLY: M2_WIFIBT; CDS_LIB: discrete; CDS_PART_NAME: R_0402-0OHM,0.05 OHM,62.5MW,195-2655-000; CDS_PHYS_PART_NAME: R_0402-0OHM,0.05 OHM,62.5MW,195-2655-000-0OHM,195-2655-000; CDS_SEC: 1; CHIPS_PART_NAME: R; DEVICE_TYPENAME: R_0402-0OHM005OHM625MW195-2655-000-0OHM195-2655-000; DRAWING: #NAME?; MAX_WATTAGE: 62.5mW; NV_PN: 195-2655-000; PATH: I82; PHYS_PAGE: 20; ROT: 0; SEC: 1; SKU: NO STUFF; TOL: 0.05 ohm; VER: 1; XY: (-3450,4350)
C114 = C#1_v2: ASSEMBLY: M2_NVME; CDS_LIB: discrete; CDS_PART_NAME: C_0603-10UF,X5R,20%,6.3V,039-0135-000; CDS_PHYS_PART_NAME: C_0603-10UF,X5R,20%,6.3V,039-0135-000-039-0135-000,10UF; CDS_SEC: 1; CHIPS_PART_NAME: C; DEVICE_TYPENAME: C_0603-10UFX5R2063V039-0135-000-039-0135-00010UF; DRAWING: #NAME?; MAT: X5R; MAX_VOLTAGE: 6.3V; NV_PN: 039-0135-000; PATH: I27; PHYS_PAGE: 21; ROT: 0; SEC: 1; SIGNAL_MODEL: nv_cap; TOL: 20%; VER: 1; XY: (-7225,5200)
C115 = C#1_v2: ASSEMBLY: M2_NVME; CDS_LIB: discrete; CDS_PART_NAME: C_0402-0.1UF,X5R,10%,6.3V,039-0007-000; CDS_PHYS_PART_NAME: C_0402-0.1UF,X5R,10%,6.3V,039-0007-000-0.1UF,039-0007-000; CDS_SEC: 1; CHIPS_PART_NAME: C; DEVICE_TYPENAME: C_0402-01UFX5R1063V039-0007-000-01UF039-0007-000; DRAWING: #NAME?; MAT: X5R; MAX_VOLTAGE: 6.3V; NV_PN: 039-0007-000; PATH: I26; PHYS_PAGE: 21; ROT: 0; SEC: 1; SIGNAL_MODEL: nv_cap; TOL: 10%; VER: 1; XY: (-6875,5200)
C116 = C: ASSEMBLY: M2_NVME; CDS_LIB: discrete; CDS_PART_NAME: C_0402-0.22UF,X5R,10%,6.3V,039-0011-000; CDS_PHYS_PART_NAME: C_0402-0.22UF,X5R,10%,6.3V,039-0011-000-0.22UF,039-0011-000; CDS_SEC: 1; DEVICE_TYPENAME: C_0402-022UFX5R1063V039-0011-000-022UF039-0011-000; DRAWING: #NAME?; MAT: X5R; MAX_VOLTAGE: 6.3V; NV_PN: 039-0011-000; PATH: I24; PHYS_PAGE: 21; ROT: 0; SEC: 1; SIGNAL_MODEL: nv_cap; TOL: 10%; VER: 2; XY: (-3150,4300)
C117 = C: ASSEMBLY: M2_NVME; CDS_LIB: discrete; CDS_PART_NAME: C_0402-0.22UF,X5R,10%,6.3V,039-0011-000; CDS_PHYS_PART_NAME: C_0402-0.22UF,X5R,10%,6.3V,039-0011-000-0.22UF,039-0011-000; CDS_SEC: 1; DEVICE_TYPENAME: C_0402-022UFX5R1063V039-0011-000-022UF039-0011-000; DRAWING: #NAME?; MAT: X5R; MAX_VOLTAGE: 6.3V; NV_PN: 039-0011-000; PATH: I32; PHYS_PAGE: 21; ROT: 0; SEC: 1; SIGNAL_MODEL: nv_cap; TOL: 10%; VER: 2; XY: (-3150,4000)
C118 = C: ASSEMBLY: M2_NVME; CDS_LIB: discrete; CDS_PART_NAME: C_0402-0.22UF,X5R,10%,6.3V,039-0011-000; CDS_PHYS_PART_NAME: C_0402-0.22UF,X5R,10%,6.3V,039-0011-000-0.22UF,039-0011-000; CDS_SEC: 1; DEVICE_TYPENAME: C_0402-022UFX5R1063V039-0011-000-022UF039-0011-000; DRAWING: #NAME?; MAT: X5R; MAX_VOLTAGE: 6.3V; NV_PN: 039-0011-000; PATH: I30; PHYS_PAGE: 21; ROT: 0; SEC: 1; SIGNAL_MODEL: nv_cap; TOL: 10%; VER: 2; XY: (-3150,3700)
C119 = C: ASSEMBLY: M2_NVME; CDS_LIB: discrete; CDS_PART_NAME: C_0402-0.22UF,X5R,10%,6.3V,039-0011-000; CDS_PHYS_PART_NAME: C_0402-0.22UF,X5R,10%,6.3V,039-0011-000-0.22UF,039-0011-000; CDS_SEC: 1; DEVICE_TYPENAME: C_0402-022UFX5R1063V039-0011-000-022UF039-0011-000; DRAWING: #NAME?; MAT: X5R; MAX_VOLTAGE: 6.3V; NV_PN: 039-0011-000; PATH: I31; PHYS_PAGE: 21; ROT: 0; SEC: 1; SIGNAL_MODEL: nv_cap; TOL: 10%; VER: 2; XY: (-3150,3400)
C120 = C: ASSEMBLY: M2_NVME; CDS_LIB: discrete; CDS_PART_NAME: C_0402-0.22UF,X5R,10%,6.3V,039-0011-000; CDS_PHYS_PART_NAME: C_0402-0.22UF,X5R,10%,6.3V,039-0011-000-0.22UF,039-0011-000; CDS_SEC: 1; DEVICE_TYPENAME: C_0402-022UFX5R1063V039-0011-000-022UF039-0011-000; DRAWING: #NAME?; MAT: X5R; MAX_VOLTAGE: 6.3V; NV_PN: 039-0011-000; PATH: I8; PHYS_PAGE: 21; ROT: 0; SEC: 1; SIGNAL_MODEL: nv_cap; TOL: 10%; VER: 2; XY: (-2700,4250)
C121 = C: ASSEMBLY: M2_NVME; CDS_LIB: discrete; CDS_PART_NAME: C_0402-0.22UF,X5R,10%,6.3V,039-0011-000; CDS_PHYS_PART_NAME: C_0402-0.22UF,X5R,10%,6.3V,039-0011-000-0.22UF,039-0011-000; CDS_SEC: 1; DEVICE_TYPENAME: C_0402-022UFX5R1063V039-0011-000-022UF039-0011-000; DRAWING: #NAME?; MAT: X5R; MAX_VOLTAGE: 6.3V; NV_PN: 039-0011-000; PATH: I21; PHYS_PAGE: 21; ROT: 0; SEC: 1; SIGNAL_MODEL: nv_cap; TOL: 10%; VER: 2; XY: (-2700,3950)
C122 = C: ASSEMBLY: M2_NVME; CDS_LIB: discrete; CDS_PART_NAME: C_0402-0.22UF,X5R,10%,6.3V,039-0011-000; CDS_PHYS_PART_NAME: C_0402-0.22UF,X5R,10%,6.3V,039-0011-000-0.22UF,039-0011-000; CDS_SEC: 1; DEVICE_TYPENAME: C_0402-022UFX5R1063V039-0011-000-022UF039-0011-000; DRAWING: #NAME?; MAT: X5R; MAX_VOLTAGE: 6.3V; NV_PN: 039-0011-000; PATH: I22; PHYS_PAGE: 21; ROT: 0; SEC: 1; SIGNAL_MODEL: nv_cap; TOL: 10%; VER: 2; XY: (-2700,3650)
C123 = C: ASSEMBLY: M2_NVME; CDS_LIB: discrete; CDS_PART_NAME: C_0402-0.22UF,X5R,10%,6.3V,039-0011-000; CDS_PHYS_PART_NAME: C_0402-0.22UF,X5R,10%,6.3V,039-0011-000-0.22UF,039-0011-000; CDS_SEC: 1; DEVICE_TYPENAME: C_0402-022UFX5R1063V039-0011-000-022UF039-0011-000; DRAWING: #NAME?; MAT: X5R; MAX_VOLTAGE: 6.3V; NV_PN: 039-0011-000; PATH: I23; PHYS_PAGE: 21; ROT: 0; SEC: 1; SIGNAL_MODEL: nv_cap; TOL: 10%; VER: 2; XY: (-2700,3350)
C144 = C#1_v2: ASSEMBLY: M2_NVME; CDS_LIB: discrete; CDS_PART_NAME: C_0402-0.1UF,X5R,10%,6.3V,039-0007-000; CDS_PHYS_PART_NAME: C_0402-0.1UF,X5R,10%,6.3V,039-0007-000-0.1UF,039-0007-000; CDS_SEC: 1; CHIPS_PART_NAME: C; DEVICE_TYPENAME: C_0402-01UFX5R1063V039-0007-000-01UF039-0007-000; DRAWING: #NAME?; MAT: X5R; MAX_VOLTAGE: 6.3V; NV_PN: 039-0007-000; PATH: I78; PHYS_PAGE: 21; ROT: 0; SEC: 1; SIGNAL_MODEL: nv_cap; TOL: 10%; VER: 1; XY: (-9200,6100)
J11 = CON_M2_PCI_EXP#1: ANGLE: 90; ASSEMBLY: M2_NVME; CDS_LIB: electro_mechanic; CDS_PART_NAME: CON_M2_PCI_EXP_SMD77_KEYM-SM3ZS067U215AM,N/A,0.5MM,90,YES,NO,N/A,N/A,NO,50V,0.5A,080-1743-000; CDS_PHYS_PART_NAME: CON_M2_PCI_EXP_SMD77_KEYM-SM3ZS067U215AM,N/A,0.5MM,90,YES,NO,N/A,N/A,NO,50V,0.5A,080-1743-000-080-1743-000; CDS_SEC: 1; DEVICE_TYPENAME: CON_M2_PCI_EXP_SMD77_KEYM-SM3ZS067U215AMNA05MM90YESNONANANO50V05A080-1743-000-080-1743-000; DRAWING: #NAME?; EMI_GROUND_TAB: N/A; GENDER: N/A; LATCHING: N/A; MAX_CURRENT: 0.5A; MAX_VOLTAGE: 50V; NV_NAME: SM3ZS067U215AM; NV_PN: 080-1743-000; PACK_TYPE: SMD77_KEYM; PATH: I1; PHYS_PAGE: 21; PITCH: 0.5mm; REFLOW: YES; ROT: 0; SEC: 1; SHIELDED: NO; SHROUDED: NO; VER: 5; XY: (-5400,4050)
MEC2 = MEC_STANDOFF: ASSEMBLY: M2_NVME; CDS_LIB: mechanic; CDS_PART_NAME: MEC_STANDOFF_SMD-SMD MECH STDF_035MM,155-0879-000; CDS_PHYS_PART_NAME: MEC_STANDOFF_SMD-SMD MECH STDF_035MM,155-0879-000-155-0879-000; CDS_SEC: 1; DEVICE_TYPENAME: MEC_STANDOFF_SMD-SMDMECHSTDF_035MM155-0879-000-155-0879-000; DRAWING: #NAME?; NV_NAME: SMD MECH STDF_035mm; NV_PN: 155-0879-000; PACK_TYPE: SMD; PATH: I82; PHYS_PAGE: 21; ROT: 0; SEC: 1; SEC_TYPE: SMD; VER: 2; XY: (-6050,2250)
R110 = R#1: ASSEMBLY: M2_NVME; CDS_LIB: discrete; CDS_PART_NAME: R_0603-0OHM,0.05 OHM,0MW,195-1765-000; CDS_PHYS_PART_NAME: R_0603-0OHM,0.05 OHM,0MW,195-1765-000-0OHM,195-1765-000; CDS_SEC: 1; CHIPS_PART_NAME: R; DEVICE_TYPENAME: R_0603-0OHM005OHM0MW195-1765-000-0OHM195-1765-000; DRAWING: #NAME?; MAX_WATTAGE: 0mW; NV_PN: 195-1765-000; PATH: I65; PHYS_PAGE: 21; ROT: 0; SEC: 1; SIGNAL_MODEL: nv_res; SKU: NO STUFF; TOL: 0.05 ohm; VER: 1; XY: (-9200,1750)
R111 = R#1: ASSEMBLY: M2_NVME; CDS_LIB: discrete; CDS_PART_NAME: R_0603-0OHM,0.05 OHM,0MW,195-1765-000; CDS_PHYS_PART_NAME: R_0603-0OHM,0.05 OHM,0MW,195-1765-000-0OHM,195-1765-000; CDS_SEC: 1; CHIPS_PART_NAME: R; DEVICE_TYPENAME: R_0603-0OHM005OHM0MW195-1765-000-0OHM195-1765-000; DRAWING: #NAME?; MAX_WATTAGE: 0mW; NV_PN: 195-1765-000; PATH: I68; PHYS_PAGE: 21; ROT: 0; SEC: 1; SIGNAL_MODEL: nv_res; SKU: NO STUFF; TOL: 0.05 ohm; VER: 1; XY: (-9200,1550)
R113 = R: ASSEMBLY: M2_NVME; CDS_LIB: discrete; CDS_PART_NAME: R_0402-47K,5 %,62.5MW,195-0599-000; CDS_PHYS_PART_NAME: R_0402-47K,5 %,62.5MW,195-0599-000-195-0599-000,47K; CDS_SEC: 1; DEVICE_TYPENAME: R_0402-47K5625MW195-0599-000-195-0599-00047K; DRAWING: #NAME?; MAX_WATTAGE: 62.5mW; NV_PN: 195-0599-000; PATH: I45; PHYS_PAGE: 21; ROT: 2; SEC: 1; SIGNAL_MODEL: nv_res; TOL: 5%; VER: 2; XY: (-8800,4450)
R114 = R: ASSEMBLY: M2_NVME; CDS_LIB: discrete; CDS_PART_NAME: R_0402-47K,5 %,62.5MW,195-0599-000; CDS_PHYS_PART_NAME: R_0402-47K,5 %,62.5MW,195-0599-000-195-0599-000,47K; CDS_SEC: 1; DEVICE_TYPENAME: R_0402-47K5625MW195-0599-000-195-0599-00047K; DRAWING: #NAME?; MAX_WATTAGE: 62.5mW; NV_PN: 195-0599-000; PATH: I39; PHYS_PAGE: 21; ROT: 2; SEC: 1; SIGNAL_MODEL: nv_res; SKU: NO STUFF; TOL: 5%; VER: 2; XY: (-8000,4600)
Y2 = OSC_4PIN: ASSEMBLY: M2_NVME; CDS_LIB: clocks; CDS_PART_NAME: OSC_4PIN_SMD_32X25-7XZ3270027,32.768KHZ,25PPM,5PPM,25PPM,15PF,086-0282-000; CDS_PHYS_PART_NAME: OSC_4PIN_SMD_32X25-7XZ3270027,32.768KHZ,25PPM,5PPM,25PPM,15PF,086-0282-000-086-0282-000,32.768KHZ; CDS_SEC: 1; DEVICE_TYPENAME: OSC_4PIN_SMD_32X25-7XZ327002732768KHZ25PPM5PPM25PPM15PF086-0282-000-086-0282-00032768KHZ; DRAWING: #NAME?; LOAD_CAPACITANCE: 15pF; NV_NAME: 7XZ3270027; NV_PN: 086-0282-000; PACK_TYPE: SMD_32X25; PATH: I75; PHYS_PAGE: 21; ROT: 0; SEC: 1; TOL: 25ppm; TOL_AGE: 5ppm; TOL_TOTAL: 25ppm; VER: 1; XY: (-9550,5600)

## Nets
GND: C108.2 C109.2 C110.2 C111.2 C114.2 C115.2 C136.2 C137.2 C138.1 C144.2 D40.2 D41.2 J10.1(GND_11) J10.7(GND_10) J10.18(GND_9) J10.33(GND_8) J10.39(GND_7) J10.45(GND_6) J10.51(GND_5) J10.57(GND_4) J10.63(GND_3) J10.69(GND_2) J10.75(GND_1) J10.76(GND_13) J10.77(GND_12) J11.1(GND_14) J11.3(GND_13) J11.9(GND_12) J11.15(GND_11) J11.21(GND_10) J11.27(GND_9) J11.33(GND_8) J11.39(GND_7) J11.45(GND_6) J11.51(GND_5) J11.57(GND_4) J11.71(GND_3) J11.73(GND_2) J11.75(GND_1) J11.76(GND_15) J11.77(GND_16) MEC1.1 MEC2.1 Q17.2(S) Q18.2(S) R148.1 R149.1 R150.1 R151.1 R152.1 R153.1 Y2.2(GND) ; also on sheet 1 2 3 7 8 9 10 11 12 13 14 15 16 17 18 19 21
VDD_1V8: R101.1 R113.1 ; also on sheet 2 3 8 9 15 19 21
VDD_3V3_SYS: C108.1 C109.1 C110.1 C111.1 C114.1 C115.1 C137.1 C144.1 J10.2(3P3V_4) J10.4(3P3V_3) J10.72(3P3V_2) J10.74(3P3V_1) J11.2(3P3V_9) J11.4(3P3V_8) J11.12(3P3V_7) J11.14(3P3V_6) J11.16(3P3V_5) J11.18(3P3V_4) J11.70(3P3V_3) J11.72(3P3V_2) J11.74(3P3V_1) J15.15(P15) J15.17(P17) R99.1 R100.1 R102.1 R103.1 R104.1 R105.1 R114.1 Y2.1(EN) Y2.4(VCC) ; also on sheet 2 3 7 8 9 12 15 16 19 20 21
BT_M2_EN: Q17.1(G) ; also on sheet 20
BT_M2_WAKE_AP: J10.20(UART_WAKE*) R102.2 ; also on sheet 20
CGND: C138.2 J15.19(SHIELD1) J15.20(SHIELD2) R148.2 R149.2 R150.2 R151.2 R152.2 R153.2
GBE_LED_ACT: R147.1 ; also on sheet 20
GBE_LED_LINK: R146.1 ; also on sheet 20
GBE_MDI0_N: J15.2(P2) ; also on sheet 20
GBE_MDI0_P: J15.1(P1) ; also on sheet 20
GBE_MDI1_N: J15.6(P6) ; also on sheet 20
GBE_MDI1_P: J15.3(P3) ; also on sheet 20
GBE_MDI2_N: J15.8(P8) ; also on sheet 20
GBE_MDI2_P: J15.7(P7) ; also on sheet 20
GBE_MDI3_N: J15.10(P10) ; also on sheet 20
GBE_MDI3_P: J15.9(P9) ; also on sheet 20
GREEN_LED: J15.16(P16) R146.2
I2C2_M2E_SCL: J10.60(I2C_CLK) R106.2
I2C2_M2E_SDA: J10.58(I2C_DATA) R107.2
I2C2_M2M_SCL: J11.40(I2C_CLK) R110.2
I2C2_M2M_SDA: J11.42(I2C_DATA) R111.2
I2C2_SCL: D41.1 R106.1 R110.1 ; also on sheet 2 21
I2C2_SDA: D40.1 R107.1 R111.1 ; also on sheet 2 21
I2S1_LRCK: J10.10(PCM_SYNC_125_WS) ; also on sheet 20
I2S1_SCLK: J10.8(PCM_CLK_12S_SCK) ; also on sheet 20
I2S1_SDIN: J10.12(PCM_IN_12S_SD_IN) ; also on sheet 20
I2S1_SDOUT: J10.14(PCM_OUT_12S_SD_OUT) ; also on sheet 20
M2_SDIO_CLK: J10.9(SDIO_CLK) R191.1
M2_SDIO_CMD: J10.11(SDIO_CMD) R190.1
M2_SDIO_D0: J10.13(SDIO_DATAO) R189.1
M2_SDIO_D1: J10.15(SDIO_DATA1) ; also on sheet 20
M2_SDIO_D2: J10.17(SDIO_DATA2) R188.1
M2_SDIO_D3: J10.19(SDIO_DATA3) R187.1
M2E_ALERT*: J10.62(ALERT*) R101.2 ; also on sheet 20
M2E_SUSCLK_32KHZ: J10.50(SUSCLK_32KHZ) ; also on sheet 19
M2M_ALERT*: J11.44(ALERT*) R113.2 ; also on sheet 20
M2M_SUSCLK_32KHZ: J11.68(SUSCLK) Y2.3(OUT)
MCT: C136.1 J15.4(P4) J15.5(P5)
PCIE0_CLK_N: J11.53(REFCLKN) ; also on sheet 19
PCIE0_CLK_P: J11.55(REFCLKP) ; also on sheet 19
PCIE0_CLKREQ: J11.52(CLKREQ*) ; also on sheet 19
PCIE0_RST: J11.50(PERST*) R114.2 ; also on sheet 19
PCIE0_RX0_N: J11.41(PERN0) ; also on sheet 19
PCIE0_RX0_P: J11.43(PERP0) ; also on sheet 19
PCIE0_RX1_N: J11.29(PERN1) ; also on sheet 19
PCIE0_RX1_P: J11.31(PERP1) ; also on sheet 19
PCIE0_RX2_N: J11.17(PERN2) ; also on sheet 19
PCIE0_RX2_P: J11.19(PERP2) ; also on sheet 19
PCIE0_RX3_N: J11.5(PERN3) ; also on sheet 19
PCIE0_RX3_P: J11.7(PERP3) ; also on sheet 19
PCIE0_TX0_M2_N: C120.1 J11.47(PETN0)
PCIE0_TX0_M2_P: C116.1 J11.49(PETP0)
PCIE0_TX0_N: C120.2 ; also on sheet 19
PCIE0_TX0_P: C116.2 ; also on sheet 19
PCIE0_TX1_M2_N: C121.1 J11.35(PETN1)
PCIE0_TX1_M2_P: C117.1 J11.37(PETP1)
PCIE0_TX1_N: C121.2 ; also on sheet 19
PCIE0_TX1_P: C117.2 ; also on sheet 19
PCIE0_TX2_M2_N: C122.1 J11.23(PETN2)
PCIE0_TX2_M2_P: C118.1 J11.25(PETP2)
PCIE0_TX2_N: C122.2 ; also on sheet 19
PCIE0_TX2_P: C118.2 ; also on sheet 19
PCIE0_TX3_M2_N: C123.1 J11.11(PETN3)
PCIE0_TX3_M2_P: C119.1 J11.13(PETP3)
PCIE0_TX3_N: C123.2 ; also on sheet 19
PCIE0_TX3_P: C119.2 ; also on sheet 19
PCIE1_CLK_N: J10.49(REFCLKNO) ; also on sheet 19
PCIE1_CLK_P: J10.47(REFCLKPO) ; also on sheet 19
PCIE1_CLKREQ: J10.53(CLKREQO*) R104.2 ; also on sheet 19
PCIE1_M2_TX0_N: C112.1 J10.37(PETNO)
PCIE1_M2_TX0_P: C113.1 J10.35(PETPO)
PCIE1_RST: J10.52(PERST0*) R100.2 ; also on sheet 19
PCIE1_RX0_N: J10.43(PERNO) ; also on sheet 19
PCIE1_RX0_P: J10.41(PERPO) ; also on sheet 19
PCIE1_TX0_N: C112.2 ; also on sheet 19
PCIE1_TX0_P: C113.2 ; also on sheet 19
PCIE_WAKE: J10.55(PEWAKEO*) J11.54(PEWAKE*) R105.2 ; also on sheet 19
POE_VC1: J15.11(P11) J19.1
POE_VC2: J15.12(P12) J19.2
POE_VC3: J15.13(P13) J19.4
POE_VC4: J15.14(P14) J19.3
SDIO_CLK: R191.2 ; also on sheet 20
SDIO_CMD: R190.2 ; also on sheet 20
SDIO_D0: R189.2 ; also on sheet 20
SDIO_D2: R188.2 ; also on sheet 20
SDIO_D3: R187.2 ; also on sheet 20
SNN_COEX1: J10.48(COEX1)
SNN_COEX2: J10.46(COEX2)
SNN_COEX3: J10.44(COEX3)
SNN_LED1_L: J10.6(LED1*)
SNN_LED2_L: J10.16(LED2*)
SNN_M2_B_65: J10.65(RESERVED_PERP1)
SNN_M2_B_67: J10.67(RESERVED_PERN1)
SNN_M2_B_71: J10.71(RESERVED_REFCLKP1)
SNN_M2_B_73: J10.73(RESERVED_REFCLKN1)
SNN_M2_E_59: J10.59(RESERVED_PETP1)
SNN_M2_E_61: J10.61(RESERVED_PETN1)
SNN_M2_E_64: J10.64(RESERVED)
SNN_M2_E_66: J10.66(UIM_SWP_PERST1*)
SNN_M2_E_68: J10.68(UIM_POWER_SNK_CLKREQ1*)
SNN_M2_E_70: J10.70(UIM_POWER_SRC_GPIO1_PEWAKE1*)
SNN_M2_WIFI_M2_EN: J10.23(SDIO_RESET*)
SNN_M2_WIFI_M2_WAKE_AP: J10.21(SDIO_WAKE*)
SNN_MDM_KEYM_NC0: J11.67(NC_1)
SNN_MDM_KEYM_NC1: J11.48(NC_2)
SNN_MDM_KEYM_NC2: J11.46(NC_3)
SNN_MDM_KEYM_NC3: J11.38(NC_4)
SNN_MDM_KEYM_NC4: J11.36(NC_5)
SNN_MDM_KEYM_NC5: J11.34(NC_6)
SNN_MDM_KEYM_NC6: J11.32(NC_7)
SNN_MDM_KEYM_NC7: J11.30(NC_8)
SNN_MDM_KEYM_NC8: J11.28(NC_9)
SNN_MDM_KEYM_NC9: J11.26(NC_10)
SNN_MDM_KEYM_NC10: J11.24(NC_11)
SNN_MDM_KEYM_NC11: J11.22(NC_12)
SNN_MDM_KEYM_NC12: J11.20(NC_13)
SNN_MDM_KEYM_NC13: J11.10(LED*)
SNN_MDM_KEYM_NC14: J11.8(NC_14)
SNN_MDM_KEYM_NC15: J11.6(NC_15)
SNN_MDM_KEYM_PEDET: J11.69(PEDET)
SNN_MDM_KEYM_RSEV1: J11.58(RESERVED_1)
SNN_MDM_KEYM_RSEV2: J11.56(RESERVED_2)
SNN_VENDOR_DEFINED1: J10.42(VENDOR_DEFINED_1)
SNN_VENDOR_DEFINED2: J10.40(VENDOR_DEFINED_2)
SNN_VENDOR_DEFINED3: J10.38(VENDOR_DEFINED_3)
UART0_CTS: J10.34(UART_CTS) ; also on sheet 21
UART0_RTS: J10.36(UART_RTS) ; also on sheet 21
UART0_RXD: J10.22(UART_RXD) ; also on sheet 21
UART0_TXD: J10.32(UART_TXD) ; also on sheet 21
USB2_AP_N: J10.5(USB_DM) ; also on sheet 20
USB2_AP_P: J10.3(USB_DP) ; also on sheet 20
W_DISABLE1: J10.56(W_DISABLE1*) Q18.3(D) R103.2
W_DISABLE1_CTRL: Q18.1(G) ; also on sheet 20
W_DISABLE2: J10.54(W_DISABLE2*) Q17.3(D) R99.2
YELLOW_LED: J15.18(P18) R147.2

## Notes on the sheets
sheet 4
- A
- B
- C
- D
- E
- F
- G
- H
- M.2 KEY-M (NVME)
- 1
- 1
- 2
- 2
- 3
- 3
- 4
- M.2 Mechanical stand-off
- 4
- 5
- 5
- NVIDIA CORPORATION
- 2701 SAN TOMAS EXPRESSWAY
- ASSEMBLY
- <ASSEMBLY_DESCRIPTION>
- SANTA CLARA, CA 95050, USA
- PAGE DETAIL
- M.2 KEY-M (NVME)
- NV_PN
- 600-13509-BASE-100
- ALL NVIDIA DESIGN SPECIFICATIONS, REFERENCE SPECIFICATIONS, REFERENCE BOARDS, FILES, DRAWINGS, DIAGNOSTICS, LISTS AND OTHER DOCUMENTS OR INFORMATION (TOGETHER AND SEPARATELY, 'MATERIALS') ARE BEING PROVIDED 'AS IS'. THE MATERIALS MAY
- CONTAIN KNOWN AND UNKNOWN VIOLATIONS OR DEVIATIONS OF INDUSTRY STANDARDS AND SPECIFICATIONS. NVIDIA MAKES NO WARRANTIES, EXPRESSED, IMPLIED, STATUTORY OR OTHERWISE WITH RESPECT TO THE MATERIALS OR OTHERWISE, AND EXPRESSLY DISCLAIMS ALL
- PCB REV
- P3509-A01
- PAGE
- 21 OF 25
- IMPLIED WARRANTIES INCLUDING, WITHOUT LIMITATION, THE WARRANTIES OF DESIGN, OF NONINFRINGEMENT, MERCHANTABILITY OR FITNESS FOR A PARTICULAR PURPOSE, OR ARISING FROM A COURSE OF DEALING, TRADE USAGE, TRADE PRACTICE, OR INDUSTRY STANDARDS.
- BOM REV
- <BOM_REV>
- DATE
- 27-NOV-2019
- A
- B
- C
- D
- E
- F
- G
- H
sheet 5
- A
- B
- C
- D
- E
- F
- G
- H
- M.2 KEY-E (WIFI/BT)
- 1
- 1
- +/-5%  2Amps
- 2
- 2
- 3
- 3
- M.2 Mechanical stand-off
- 4
- 4
- 5
- 5
- NVIDIA CORPORATION
- 2701 SAN TOMAS EXPRESSWAY
- ASSEMBLY
- <ASSEMBLY_DESCRIPTION>
- SANTA CLARA, CA 95050, USA
- PAGE DETAIL
- M.2 KEY-E (WIFI/BT)
- NV_PN
- 600-13509-BASE-100
- ALL NVIDIA DESIGN SPECIFICATIONS, REFERENCE SPECIFICATIONS, REFERENCE BOARDS, FILES, DRAWINGS, DIAGNOSTICS, LISTS AND OTHER DOCUMENTS OR INFORMATION (TOGETHER AND SEPARATELY, 'MATERIALS') ARE BEING PROVIDED 'AS IS'. THE MATERIALS MAY
- CONTAIN KNOWN AND UNKNOWN VIOLATIONS OR DEVIATIONS OF INDUSTRY STANDARDS AND SPECIFICATIONS. NVIDIA MAKES NO WARRANTIES, EXPRESSED, IMPLIED, STATUTORY OR OTHERWISE WITH RESPECT TO THE MATERIALS OR OTHERWISE, AND EXPRESSLY DISCLAIMS ALL
- PCB REV
- P3509-A01
- PAGE
- 20 OF 25
- IMPLIED WARRANTIES INCLUDING, WITHOUT LIMITATION, THE WARRANTIES OF DESIGN, OF NONINFRINGEMENT, MERCHANTABILITY OR FITNESS FOR A PARTICULAR PURPOSE, OR ARISING FROM A COURSE OF DEALING, TRADE USAGE, TRADE PRACTICE, OR INDUSTRY STANDARDS.
- BOM REV
- <BOM_REV>
- DATE
- 27-NOV-2019
- A
- B
- C
- D
- E
- F
- G
- H
sheet 6
- A
- B
- C
- D
- E
- F
- G
- H
- GIGABIT ETHERNET W/ POE
- 1
- 1
- 2
- 2
- Sprinkle around CGND shape
- 3
- 3
- OPTIONAL POE HDR
- If = 10mA
- GRN LED: Vf = 2.2V
- 4
- 4
- YEL LED: Vf = 2.1V
- 5
- 5
- NVIDIA CORPORATION
- 2701 SAN TOMAS EXPRESSWAY
- ASSEMBLY
- <ASSEMBLY_DESCRIPTION>
- SANTA CLARA, CA 95050, USA
- PAGE DETAIL
- ETHERNET
- NV_PN
- 600-13509-BASE-100
- ALL NVIDIA DESIGN SPECIFICATIONS, REFERENCE SPECIFICATIONS, REFERENCE BOARDS, FILES, DRAWINGS, DIAGNOSTICS, LISTS AND OTHER DOCUMENTS OR INFORMATION (TOGETHER AND SEPARATELY, 'MATERIALS') ARE BEING PROVIDED 'AS IS'. THE MATERIALS MAY
- CONTAIN KNOWN AND UNKNOWN VIOLATIONS OR DEVIATIONS OF INDUSTRY STANDARDS AND SPECIFICATIONS. NVIDIA MAKES NO WARRANTIES, EXPRESSED, IMPLIED, STATUTORY OR OTHERWISE WITH RESPECT TO THE MATERIALS OR OTHERWISE, AND EXPRESSLY DISCLAIMS ALL
- PCB REV
- P3509-A01
- PAGE
- 19 OF 25
- IMPLIED WARRANTIES INCLUDING, WITHOUT LIMITATION, THE WARRANTIES OF DESIGN, OF NONINFRINGEMENT, MERCHANTABILITY OR FITNESS FOR A PARTICULAR PURPOSE, OR ARISING FROM A COURSE OF DEALING, TRADE USAGE, TRADE PRACTICE, OR INDUSTRY STANDARDS.
- BOM REV
- <BOM_REV>
- DATE
- 27-NOV-2019
- A
- B
- C
- D
- E
- F
- G
- H
